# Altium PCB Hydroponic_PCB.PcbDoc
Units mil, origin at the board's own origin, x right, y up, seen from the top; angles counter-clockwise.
Board outline 3600 x 3940 mil, 4 copper layers (SIG 1, GND, SIG 2, PWR), stack 62.508 mil thick; 44 components, 31 nets, 139 pads, 68 vias.
Unrouted connection lines stored in the file: 11.
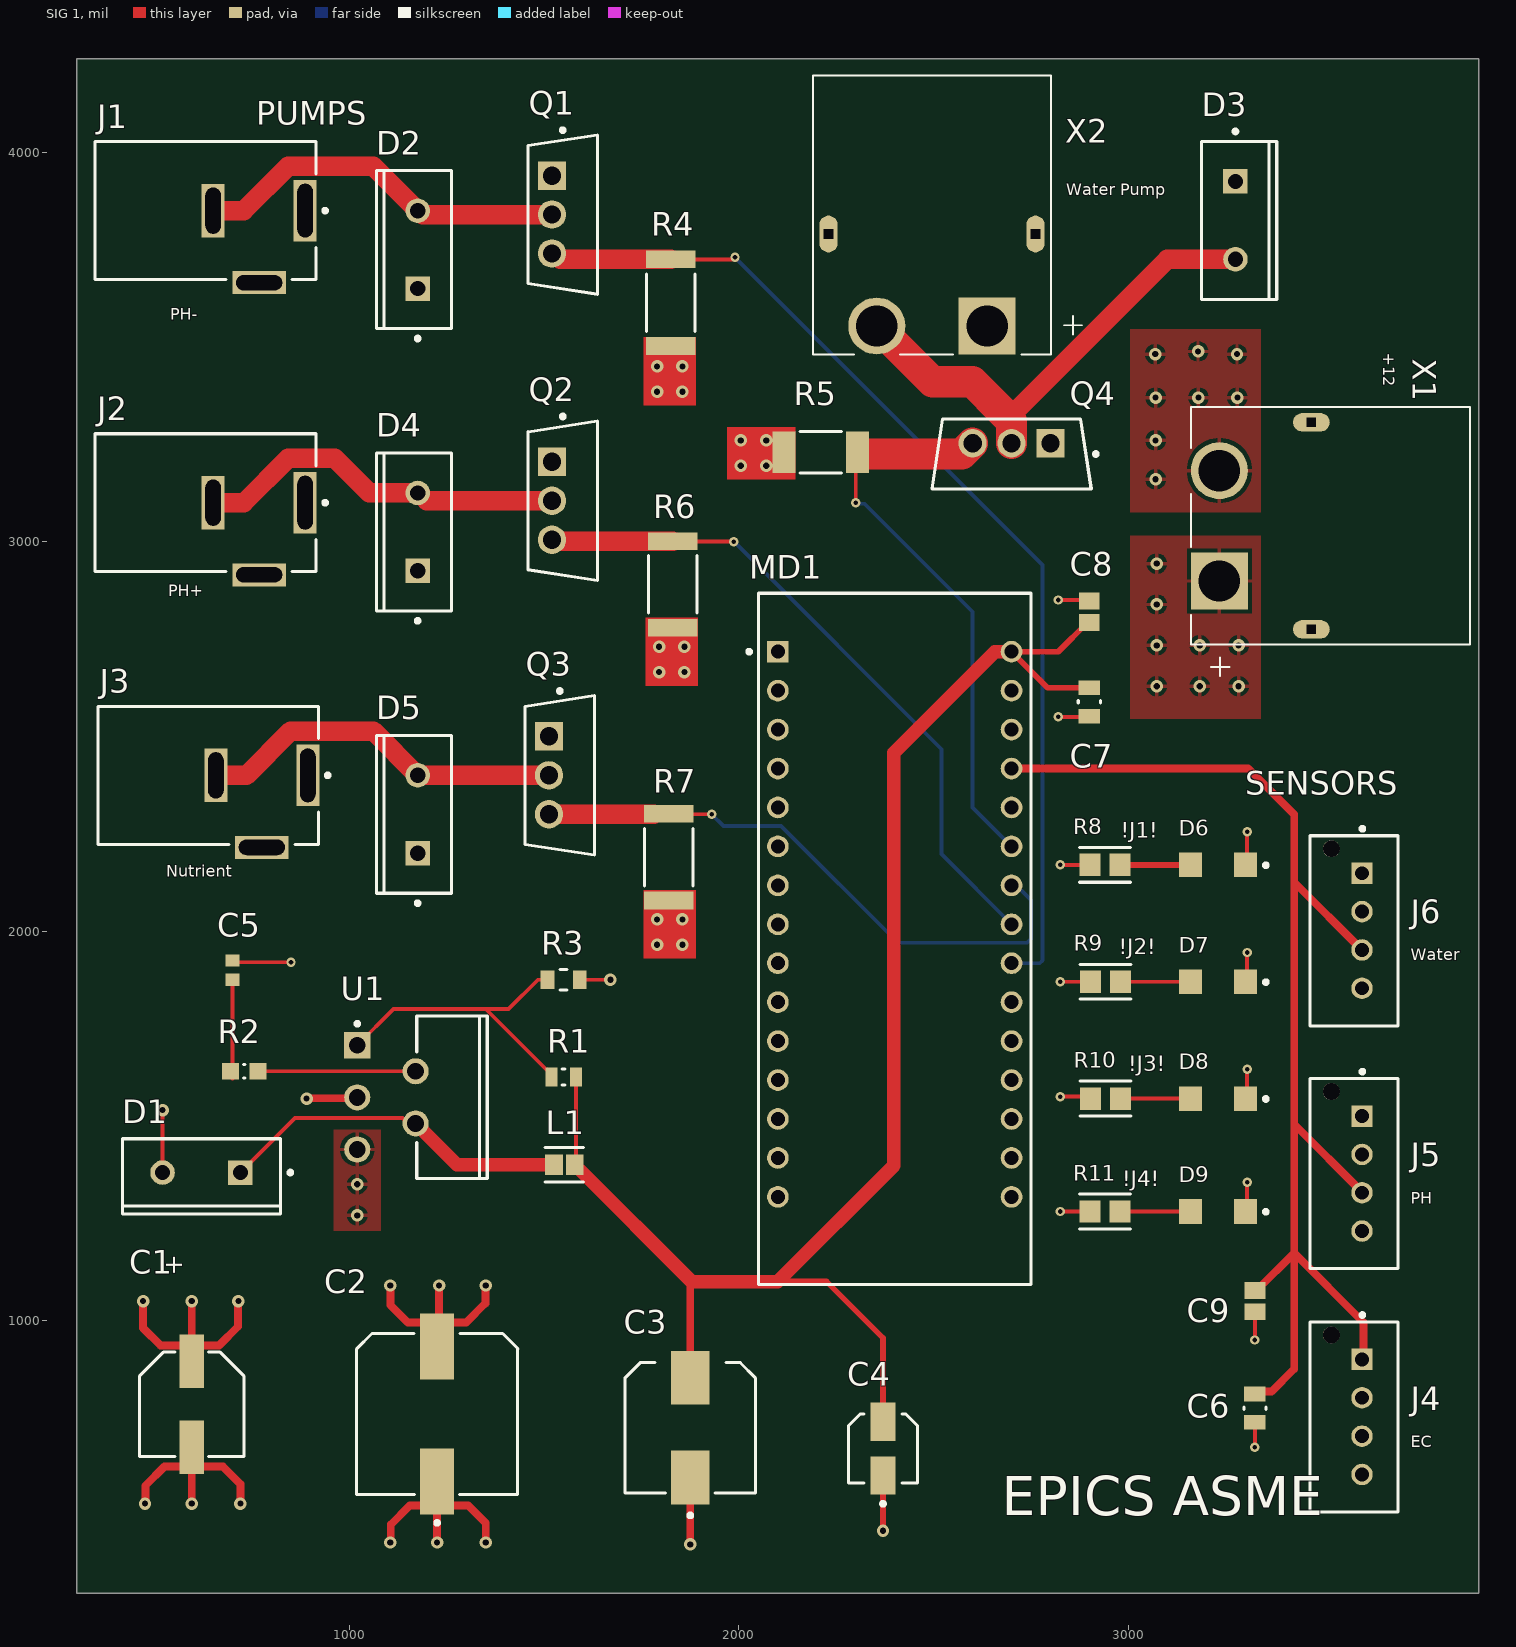
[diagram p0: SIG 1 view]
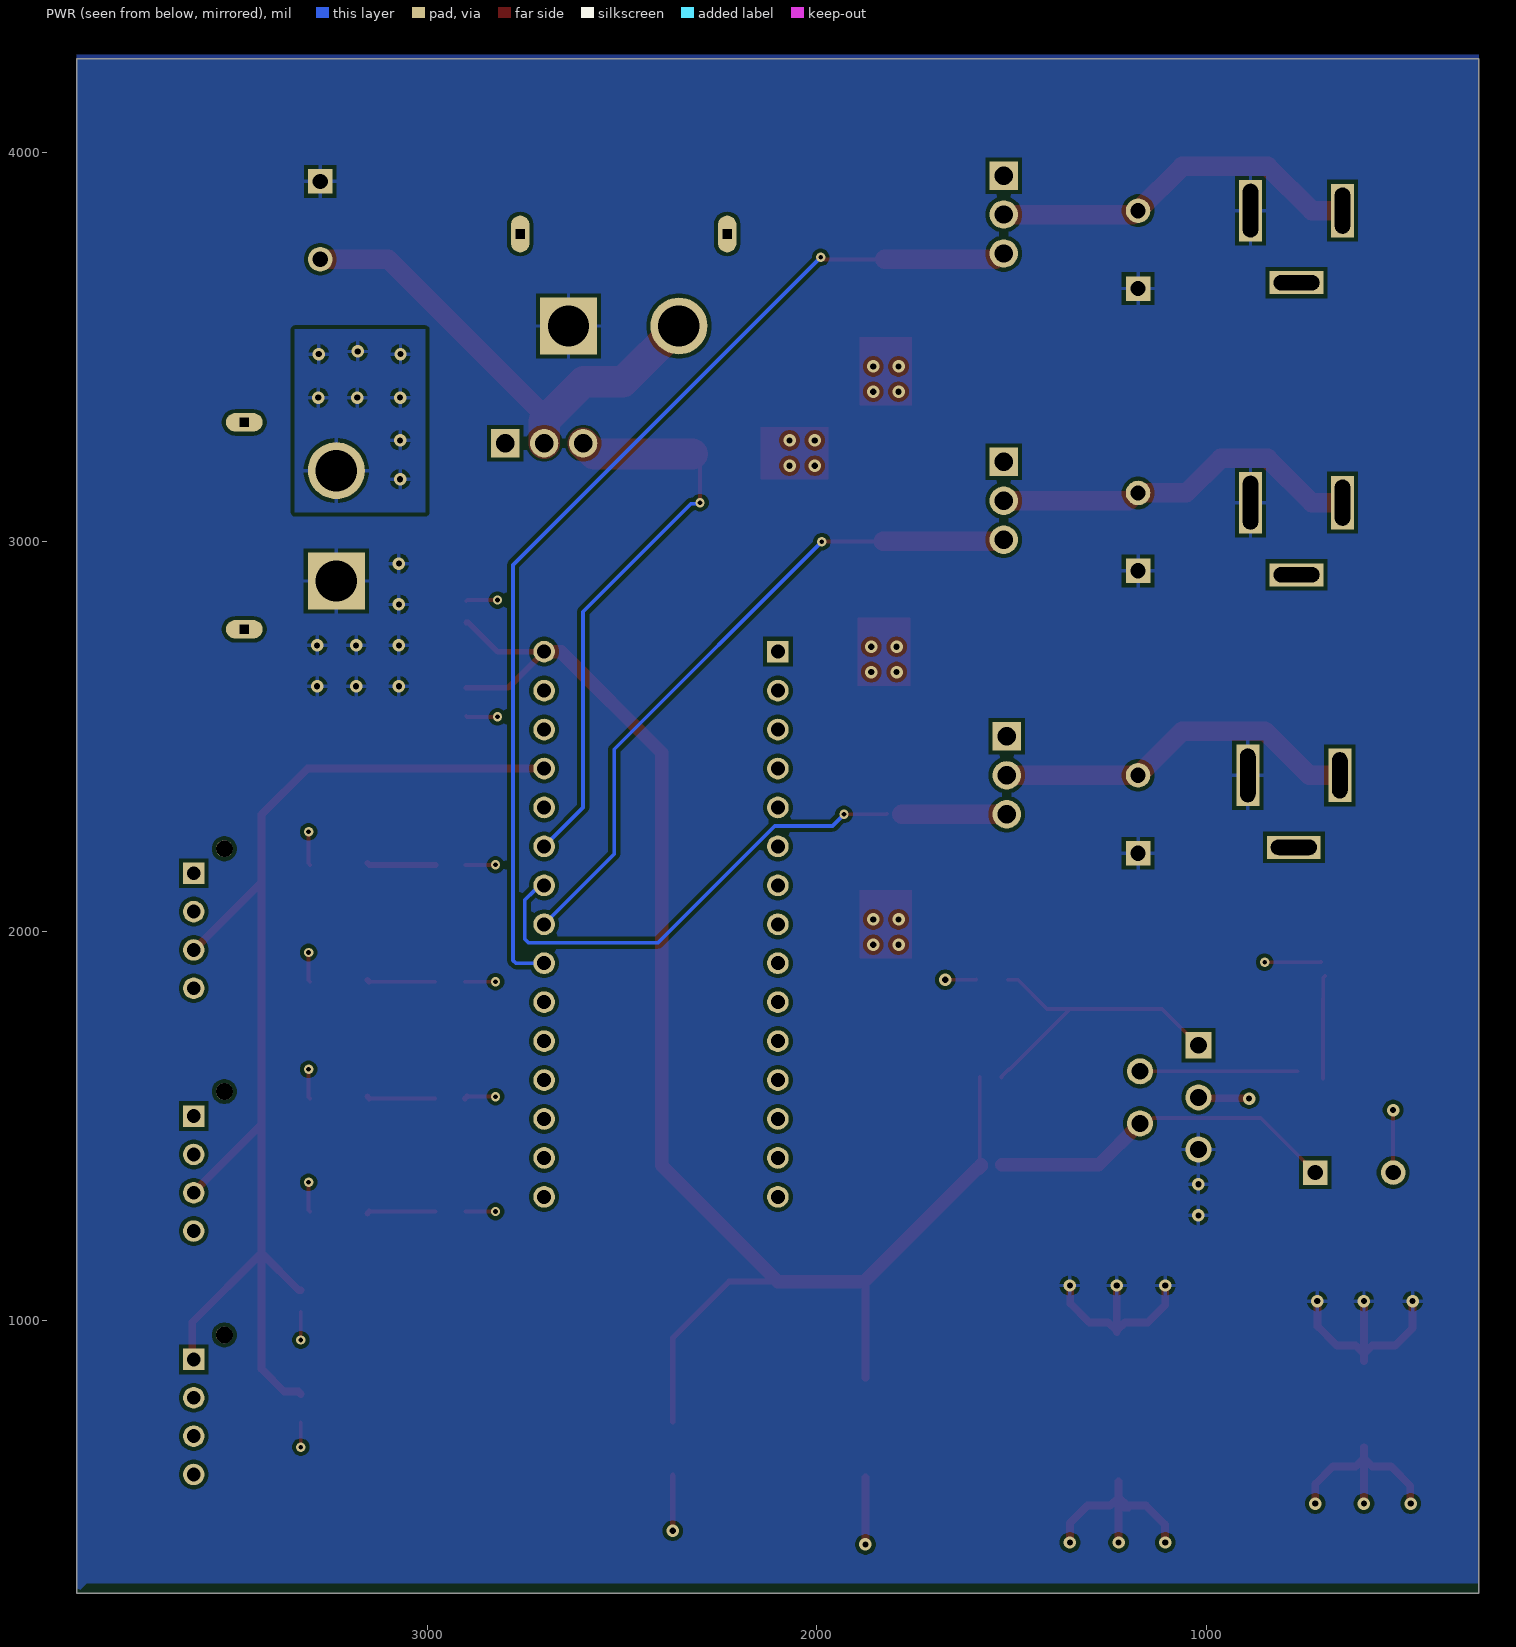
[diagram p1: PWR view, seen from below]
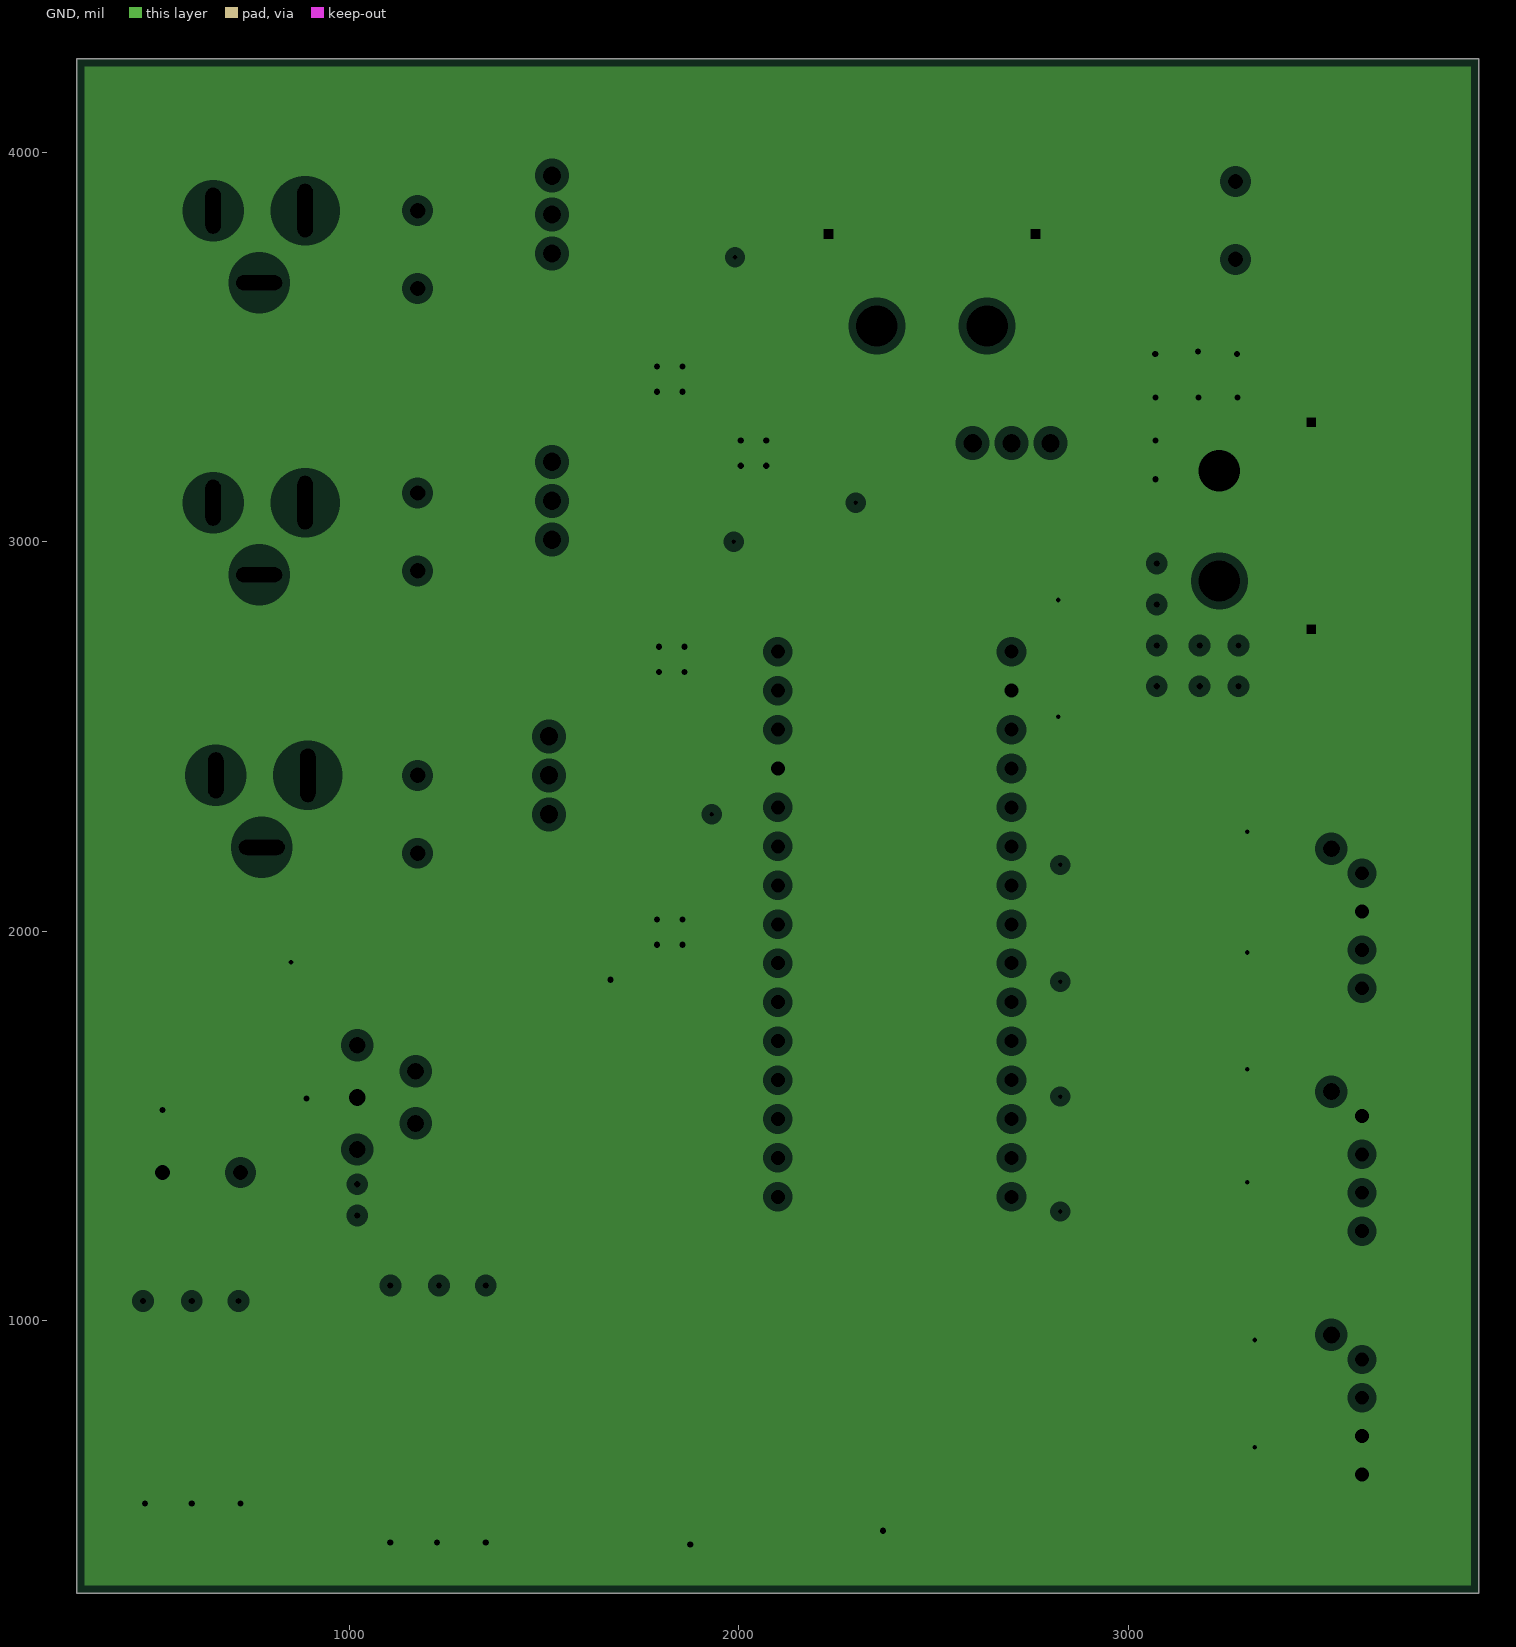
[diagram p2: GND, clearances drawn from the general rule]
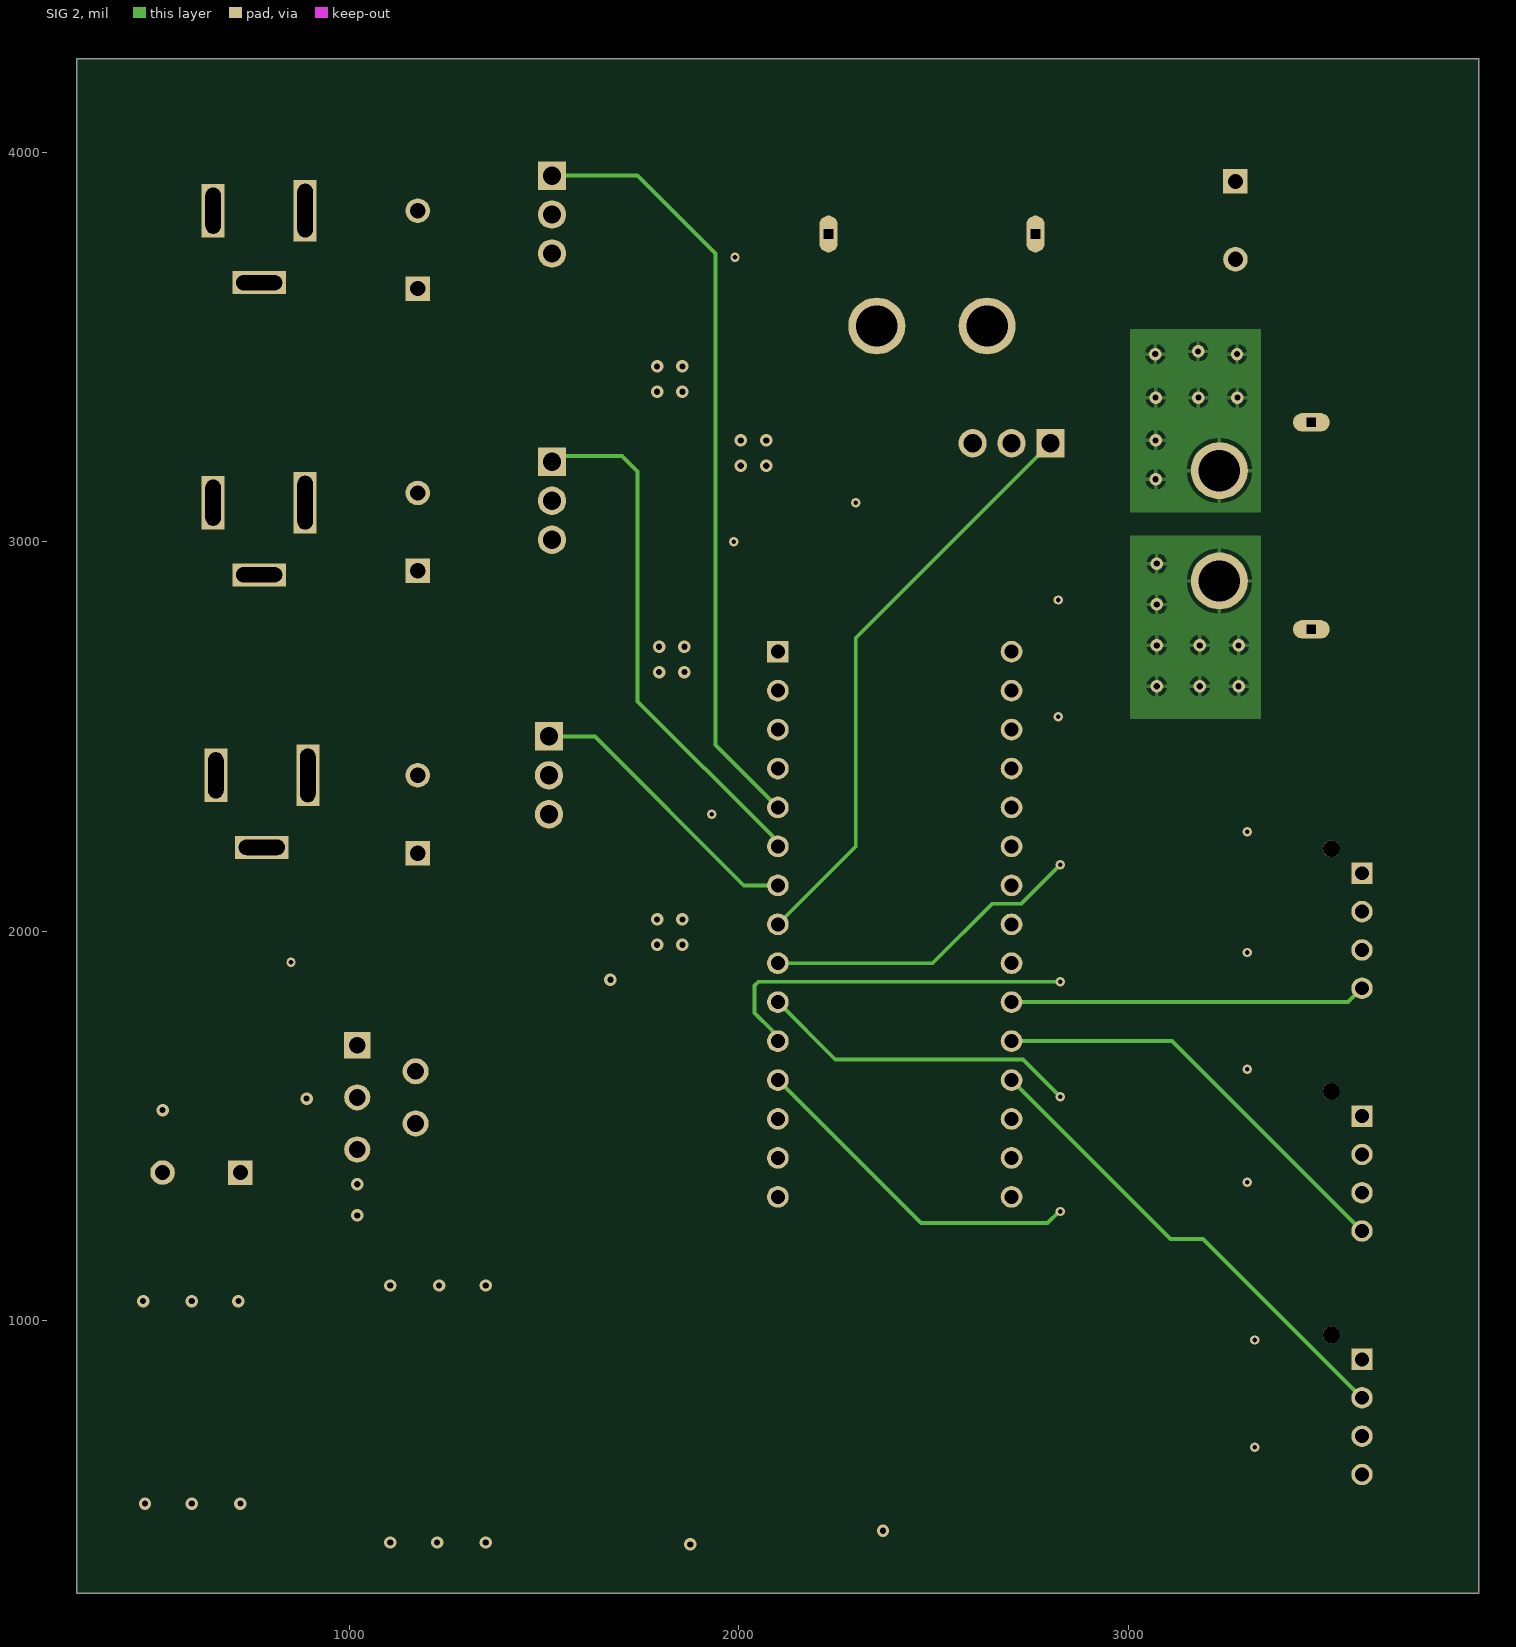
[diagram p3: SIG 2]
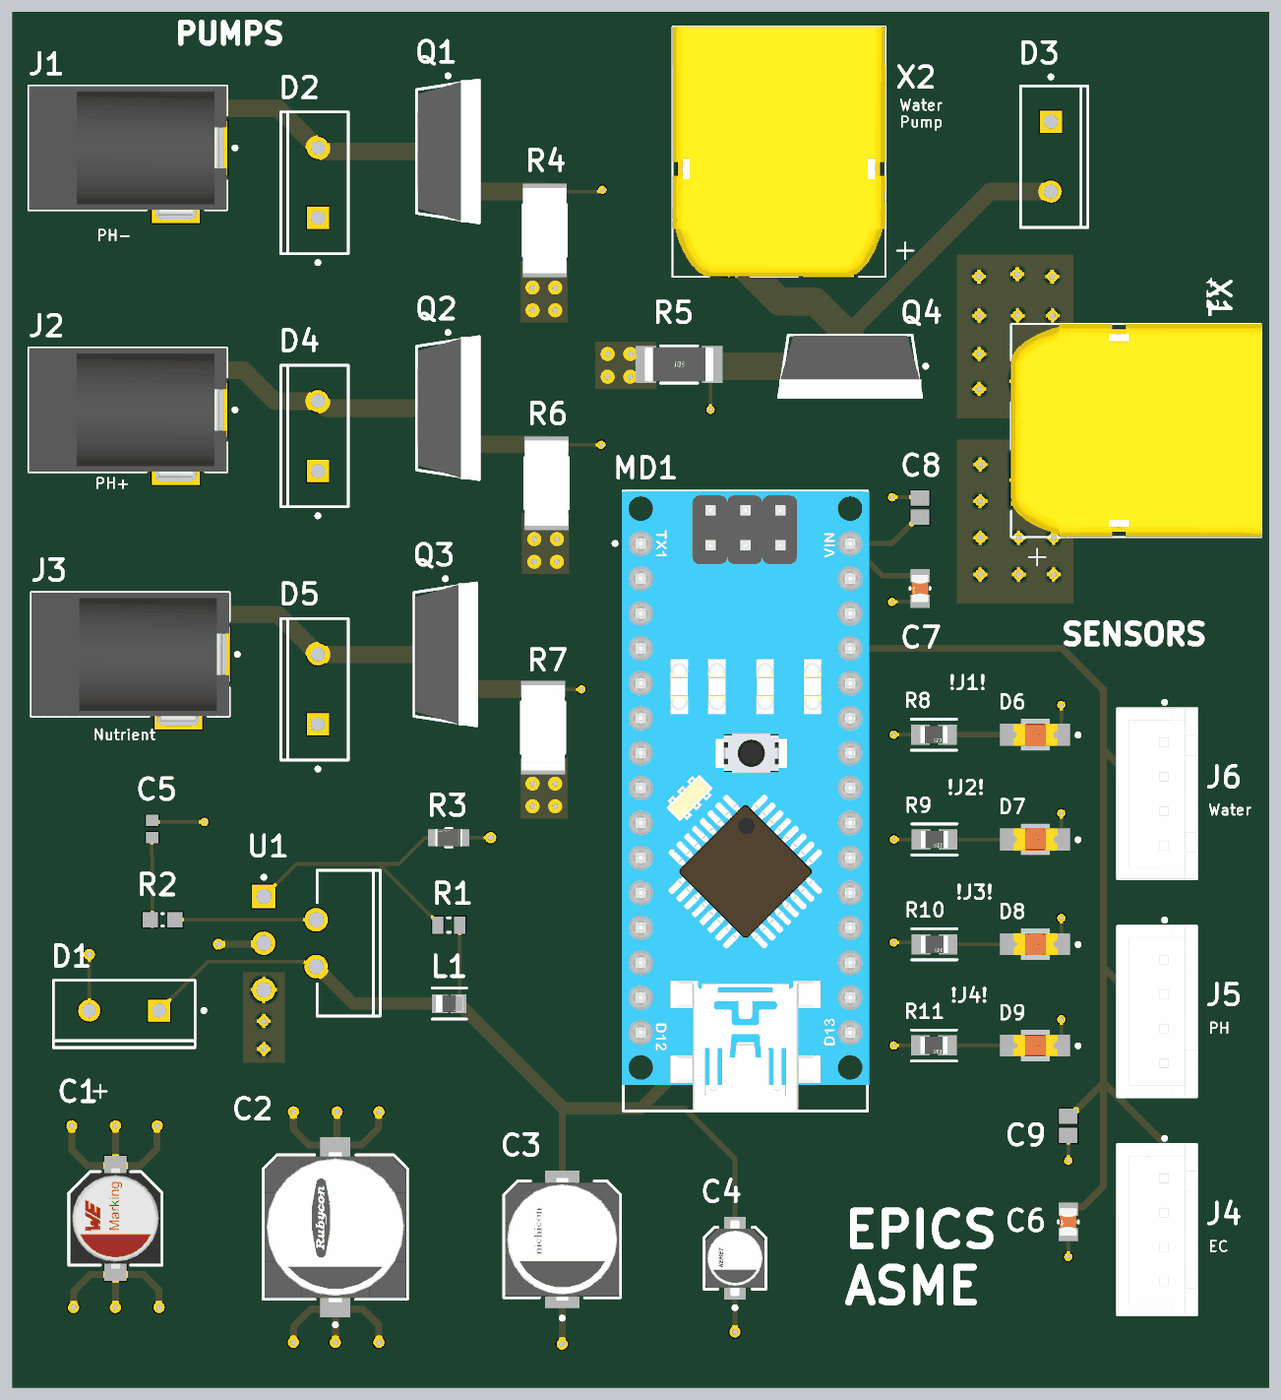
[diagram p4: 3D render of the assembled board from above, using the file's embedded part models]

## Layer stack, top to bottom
Top Solder: solder mask 0.4, Solder Resist, Dk 3.5
SIG 1: signal copper 1.4
Dielectric 1: prepreg 8.2, 7628, Dk 4.5
GND: plane copper 0.689, net GND
Dielectric 2: core 41.93, S1000-2M, Dk 4.3
SIG 2: signal copper 0.689
Dielectric 3: prepreg 8.2, 7628, Dk 4.5
PWR: signal copper 1.4
Bottom Solder: solder mask 0.4, Solder Resist, Dk 3.5

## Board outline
300,300 300,4240 3900,4240 3900,300

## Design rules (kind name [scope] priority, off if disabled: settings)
Clearance Components [InComponent('L1') OR InComponent('C5') OR InComponent('C8') OR InComponent('C9') OR InComponent('R2')] p1: gap=2 ignorepadtopadclearanceinfootprint=FALSE
Clearance GND_clearance [OnLayer('GND')] p2: gap=10 ignorepadtopadclearanceinfootprint=FALSE
Clearance [All] p3: gap=10 ignorepadtopadclearanceinfootprint=FALSE
HoleSize [All] p1: absolutevalues=TRUE maxlimit=150 minlimit=1 maxpercent=80.000 minpercent=20.000
MinimumSolderMaskSliver [All] p1: minsoldermaskwidth=3
PlaneClearance [All] p1: clearance=20
PlaneConnect [All] p1: planeconnectstyle=Relief reliefexpansion=20 reliefentries=4 reliefconductorwidth=10 reliefairgap=10
PolygonConnect [All] p1: connectstyle=Relief reliefconductorwidth=10 reliefentries=4 polygonreliefangle="90 Angle" airgapwidth=10
RoutingVias [All] p1: holewidth=12 width=24 viastyle="Through Hole" minholewidth=10 minwidth=18 maxholewidth=28 maxwidth=50
SilkToSolderMaskClearance [IsPad] p1: minsilkscreentomaskgap=3 clearancetoexposedcopper=TRUE
SolderMaskExpansion [All] p1: expansion=4 istentingtop=FALSE
SupplyNets "Schematic Supply Nets_3" [InNet('+7')] p1: voltage=0.000
SupplyNets "Schematic Supply Nets_2" [InNet('+12')] p2: voltage=0.000
SupplyNets "Schematic Supply Nets_1" [InNet('+5')] p3: voltage=0.000
SupplyNets "Schematic Supply Nets" [InNet('GND')] p4: voltage=0.000
Width [All] p1: maxlimit=100 minlimit=10 preferedwidth=10
25 further rules are at their usual default settings.

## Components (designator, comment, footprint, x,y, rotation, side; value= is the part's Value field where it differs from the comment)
C1 "220 uF" WCAP-ASLL_D6.3H7.7 595,785 r90 top
C2 "100 uF" FP-TGV10X10_5-MFG 1225,760 r90 top
C3 "47 uF" FP-UUX1H470MNL6GS-MFG 1875,725 r90 top
C4 "10 uF" FP-EDK9B-MFG 2370,671.1 r90 top value=10uF
C5 "10 nF" CAPC1608X87X35LL15T15 700,1900 r90 top
C6 "1 uF" FP-CC0805-0_85-MFG 3325,775 r270 top
C7 "1 uF" FP-CC0805-0_85-MFG 2900,2588.58 r270 top
C8 "100 nF" CAPC2013X140X50LL20T25 2900,2820 r270 top
C9 "100 nF" CAPC2013X140X50LL20T25 3325,1050 r90 top
D1 "MBR1060G" ONSC-TO-220-2-221B-04_E 620,1380 r270 top
D2 "MBR1060G" ONSC-TO-220-2-221B-04_E 1175,3750 r180 top
D3 "MBR1060G" ONSC-TO-220-2-221B-04_E 3275,3825 r0 top
D4 "MBR1060G" ONSC-TO-220-2-221B-04_E 1175,3025 r180 top
D5 "MBR1060G" ONSC-TO-220-2-221B-04_E 1175,2300 r180 top
D6 "LTST-C230EKT" FP-LTST-C230EKT-MFG 3230,2170 r180 top
D7 "LTST-C230EKT" FP-LTST-C230EKT-MFG 3230,1870 r180 top
D8 "LTST-C230EKT" FP-LTST-C230EKT-MFG 3230,1570 r180 top
D9 "LTST-C230EKT" FP-LTST-C230EKT-MFG 3230,1280 r180 top
J1 "PJ-002A" CUI-PJ-002A_V 768.11,3850 r180 top
J2 "PJ-002A" CUI-PJ-002A_V 768.11,3100 r180 top
J3 "PJ-002A" CUI-PJ-002A_V 775,2400 r180 top
J4 "PH Sensor Connector" FP-B4B-XH-AM_LF_SN-MFG 3579.33,752.36 r90 top
J5 "EC Sensor Connector" FP-B4B-XH-AM_LF_SN-MFG 3579.33,1377.36 r90 top
J6 "Water sensor 1" FP-B4B-XH-AM_LF_SN-MFG 3579.33,2000.79 r90 top
L1 "100 uH" FP-LQM21DH_70-IPC_C 1551.61,1400 r0 top
MD1 "A000005" FP-A000005-MFG 2400,1980 r0 top
Q1 "IRLZ44NPbF" FP-PG-TO220-3-MFG 1547.76,3840 r0 top
Q2 "IRLZ44NPbF" FP-PG-TO220-3-MFG 1547.76,3105 r0 top
Q3 "IRLZ44NPbF" FP-PG-TO220-3-MFG 1540,2400 r0 top
Q4 "IRLZ44NPbF" FP-PG-TO220-3-MFG 2700,3225 r270 top
R1 "1k" RESC2013X60X35LL10T20 1550,1625 r0 top
R2 "2.7k" RESC0603(1608)_M 730,1640 r0 top value="2700.00 Ohm"
R3 "2.2k" FP-AC0805-MFG 1550,1875 r180 top value=2.2KΩ
R4 "1" FP-CRCW2512-e3-IPC_C 1825,3613.75 r270 top
R5 "0.1" FP-CSRN2010-IPC_A 2210,3230 r180 top
R6 "1" FP-CRCW2512-e3-IPC_C 1830,2890 r270 top
R7 "1" FP-CRCW2512-e3-IPC_C 1820,2190 r270 top
R8 "220" FP-RMCF0805-IPC_A 2940,2170 r0 top
R9 "220" FP-RMCF0805-IPC_A 2941.58,1870 r0 top
R10 "220" FP-RMCF0805-IPC_A 2941.58,1570 r0 top
R11 "220" FP-RMCF0805-IPC_A 2940,1280 r0 top
U1 "LT1076IT" LT-T-5-S 1095,1573.07 r0 top
X1 "X1" PCBComponent_1 1631.26,1524.84 r90 top
X2 "X2" PCBComponent_1 4011.65,1951.26 r180 top

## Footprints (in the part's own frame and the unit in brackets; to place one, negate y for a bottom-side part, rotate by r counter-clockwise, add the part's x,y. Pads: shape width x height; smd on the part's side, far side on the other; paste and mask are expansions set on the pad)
CAPC1608X87X35LL15T15 [mm] "Chip Capacitor, 2-Leads, Body 1.60x0.80mm, IPC High Density"
  rect 0.8x0.9 smd: 1(-0.625,0) 2(0.625,0)
  body extent -0.87,-0.48 0.87,0.48, height 0.87
CAPC2013X140X50LL20T25 [mm] "Chip Capacitor, 2-Leads, Body 2.00x1.25mm, IPC High Density"
  rect 1.1x1.35 smd: 1(-0.7,0) 2(0.7,0)
  body extent -1.1,-0.72 1.1,0.72, height 1.4
CUI-PJ-002A_V [mm] "THD, 3-Leads, Body 14.4x9mm, Height 11mm"
  rect 1.5x4 hole 1 slot 3.5 at 90 deg: 1(-3,0)
  rect 1.5x3.5 hole 1 slot 3 at 90 deg: 2(3,0)
  rect 3.5x1.5 hole 1 slot 3 at 0 deg: 3(0,4.7)
  silkscreen extent -4.43,-4.5 10.7,4.5, body extent -3.7,-4.5 10.7,4.9, height 11
FP-A000005-MFG [mil]
  rect 55.67x55.67 hole 35.98 paste-99999 mask+0: 1(-300,737.5)
  round 55.67 hole 35.98 paste-99999 mask+0: 2(-300,637.5) 3(-300,537.5) 4(-300,437.5) 5(-300,337.5) 6(-300,237.5) 7(-300,137.5) 8(-300,37.5) 9(-300,-62.5) 10(-300,-162.5) 11(-300,-262.5) 12(-300,-362.5) 13(-300,-462.5) 14(-300,-562.5) 15(-300,-662.5) 16(300,-662.5) 17(300,-562.5) 18(300,-462.5) 19(300,-362.5) 20(300,-262.5) 21(300,-162.5) 22(300,-62.5) 23(300,37.5) 24(300,137.5) 25(300,237.5) 26(300,337.5) 27(300,437.5) 28(300,537.5) 29(300,637.5) 30(300,737.5)
  silkscreen extent -379,-888 350,888, body extent -354,-891 354,891, height 10
FP-AC0805-MFG [mm]
  rect 0.9x1.2 smd paste+0 mask+0: 1(-1.05,0) 2(1.05,0)
  silkscreen extent -0.23,-0.67 0.23,0.67, body extent -1.6,-0.77 1.6,0.77, height 0.25
FP-B4B-XH-AM_LF_SN-MFG [mm]
  rect 1.4x1.4 hole 0.9 paste-2539.97 mask+0: 1(3.75,-0.525)
  round 1.4 hole 0.9 paste-2539.97 mask+0: 2(1.25,-0.525) 3(-1.25,-0.525) 4(-3.75,-0.525)
  round 1.1 hole 1.1 unplated paste-2539.97 mask+0: ""(5.35,1.475)
  silkscreen extent -6.2,-2.88 6.77,2.88, body extent -6.3,-2.98 6.3,2.98, height 0.25
FP-CC0805-0_85-MFG [mm]
  rect 0.95x1.4 smd paste+0 mask+0: 1(-0.925,0) 2(0.925,0)
  silkscreen extent -0.08,-0.72 0.08,0.72, body extent -1.6,-1.05 1.6,1.05, height 0.25
FP-CRCW2512-e3-IPC_C [mil]
  rect 45.47x126.31 smd paste+0 mask+0: 1(-111.25,0) 2(111.25,0)
  silkscreen extent -74,-62 74,62, body extent -138,-69 138,69, height 10
FP-CSRN2010-IPC_A [mil]
  rect 59.24x106.62 smd paste+0 mask+0: 1(-94.52,0) 2(94.52,0)
  silkscreen extent -53,-53 53,53, body extent -144,-73 144,73, height 10
FP-EDK9B-MFG [mm]
  rect 2.5x1.6 smd paste+0 mask+0: 1(-1.75,0) 2(1.75,0)
  silkscreen extent -3.72,-2.25 2.25,2.25, body extent -3.25,-2.5 3.25,2.5, height 0.25
FP-LQM21DH_70-IPC_C [mil]
  rect 45.45x53.39 smd paste+0 mask+0: 1(-26.61,0) 2(26.61,0)
  silkscreen extent -49,-44 49,44, body extent -53,-32 53,32, height 10
FP-LTST-C230EKT-MFG [mm]
  rect 1.5x1.6 smd paste+0 mask+0: 1(-1.8,0) 2(1.8,0)
  silkscreen extent -3.25,-0.1 -3,0.15, body extent -2.65,-0.95 2.65,0.95, height 0.25
FP-PG-TO220-3-MFG [mm]
  rect 1.85x1.85 hole 1.2 paste-2539.97 mask+0: 1(-0.705,2.54)
  round 1.85 hole 1.2 paste-2539.97 mask+0: 2(-0.705,0) 3(-0.705,-2.54)
  silkscreen extent -2.27,-5.2 2.27,5.62, body extent -2.37,-5.55 2.37,5.55, height 0.25
FP-RMCF0805-IPC_A [mil]
  rect 53.33x57.56 smd paste+0 mask+0: 1(-38.42,0) 2(38.42,0)
  silkscreen extent -65,-45 65,45, body extent -85,-48 85,48, height 10
FP-TGV10X10_5-MFG [mm]
  rect 4.3x2.2 smd paste+0 mask+0: 1(-4.4,0) 2(4.4,0)
  silkscreen extent -7.22,-5.28 5.25,5.25, body extent -6.8,-5.5 6.8,5.5, height 0.25
FP-UUX1H470MNL6GS-MFG [mm]
  rect 3.5x2.5 smd paste+0 mask+0: 1(-3.25,0) 2(3.25,0)
  silkscreen extent -5.85,-4.25 4.26,4.25, body extent -5.25,-4.5 5.25,4.5, height 0.25
LT-T-5-S [mm] "FM, 5-Leads, Body 10.55x4.6mm, Pitch 1.7mm"
  rect 1.7x1.7 hole 1.1: 1(-1.905,3.4)
  round 1.7 hole 1.1: 2(1.905,1.7) 3(-1.905,0) 4(1.905,-1.7) 5(-1.905,-3.4)
  silkscreen extent -2.03,-5.3 6.58,5.3, body extent -2.13,-5.27 6.58,5.28, height 22.23
ONSC-TO-220-2-221B-04_E [mm] "FM, 2-Leads, Body 10.3x4.85mm, Pitch 5.08mm"
  rect 1.6x1.6 hole 1: 1(0,2.54)
  round 1.6 hole 1: 3(0,-2.54)
  silkscreen extent -2.2,-5.15 2.7,5.93, body extent -2.18,-5.15 2.67,5.15, height 19.05
PCBComponent_1 [mm]
  rect 3.716x3.716 / inner round 3.716 / far side rect 3.716x3.716 hole 2.7 mask+0.102: 1(34.904,-40.704)
  round 3.716 hole 2.7 mask+0.102: 2(42.104,-40.704)
  oval 1.2x2.4 hole 0.6 square mask+0.102: SH1(31.754,-46.704) SH2(45.254,-46.704)
  silkscreen extent 28.7,-57.05 46.25,-38.85, body extent 30.75,-57.05 46.25,-38.85, height 8.4
RESC0603(1608)_M [mm] "Chip Resistor, Body 1.6x0.8mm, IPC Low Density"
  rect 1.1x1.1 smd: 1(-0.9,0) 2(0.9,0)
  silkscreen extent -0.05,-0.45 0.05,0.45, body extent -0.85,-0.47 0.85,0.47, height 0.6
RESC2013X60X35LL10T20 [mm] "Chip Resistor, 2-Leads, Body 2.00x1.25mm, IPC High Density"
  rect 0.8x1.25 smd: 1(-0.8,0) 2(0.8,0)
  silkscreen extent -0.1,-0.53 0.1,0.53, body extent -1.05,-0.67 1.05,0.67, height 0.6
WCAP-ASLL_D6.3H7.7 [mm] "Aluminium Electrolytic V-Chip SMT Capacitors, 6.3x7.7mm"
  rect 3.5x1.6 smd: 1(2.8,0) 2(-2.8,0)
  silkscreen extent -3.4,-3.4 3.4,3.4, body extent -3.65,-3.3 3.65,3.3, height 7.7

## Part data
C1: library part CMP-03913-53914500-3, Capacitance=220µF, Case/Package=Radial, ESR (Equivalent Series Resistance)=246.927mΩ, Insulation Resistance=454.545kΩ, Leakage Current=13.86µA, Max Operating Temperature=105°C, Min Operating Temperature=-55°C, Ripple Current=280mA, Tolerance=20%, Voltage Rating=6.3V
C2: library part CMP-35376-000017-1, "CAP ALUM 100UF 20% 35V SMD"
C3: library part CMP-12462-000056-1, "CAP ALUM 47UF 20% 50V SMD", Capacitance=47uF, Case/Package=Radial, Leakage Current=70.5uA, Max Operating Temperature=105°C, Min Operating Temperature=-55°C, Package Quantity=1, Ripple Current=167mA, Tolerance=20%, Voltage=50V
C4: library part CMP-03015-000003-1, "CAP ALUM 10UF 20% 35V SMD", Capacitance=10uF, Leakage Current=3.5uA, Manufacturer=Kemet, Manufacturer Part Number=EDK106M035A9BAA, Package=EDK9B, Ripple Current=24mA, Temperature="-40°C to +85°C", Temperature Range High=+85°C, Temperature Range Low=-40°C, Tolerance=20%, Voltage Rating=35V
C5: library part CMP-2006-03842-1, Manufacturer=Kemet, Part Number=C0603S103K4RACTU
C6 C7: library part CMP-03422-000746-1, "CAP CER 1UF 10V X5R 0805", Manufacturer=Yageo, Manufacturer Part Number=CC0805KKX5R6BB105, Package=CC0805-0.85, Temperature="-30°C to +85°C", Temperature Characteristic=X5R, Temperature Range High=+85°C, Temperature Range Low=-30°C, Tolerance=0.1, Voltage Rating="10 V"
C8 C9: library part CMP-2007-04740-1, Manufacturer="AVX Interconnect / Elco", Part Number=08051C104M4Z2A
D1 D2 D3 D4 D5: library part CMP-1055-00607-1, "SWITCHMODE(TM) Power Rectifier, 2-Pin TO-220, Pb-Free, Tube", Manufacturer="On Semiconductor"
D6 D7 D8 D9: library part CMP-22017-000030-1, "LED RED CLEAR CHIP SMD", Case Code (Imperial)=1206, Case Code (Metric)=3216, Color=Red, Forward Current=30mA, Forward Voltage=2V, Lens Color=Colorless, Max Operating Temperature=85°C, Min Operating Temperature=-55°C, Package Quantity=1, Power Dissipation=100mW, Reverse Voltage=5V, Test Current=10mA
J1 J2 J3: library part CMP-2000-06895-2, "Through Hole Right Angle DC Power Jack, 2.5 A, 2 mm Center Pin, 3 Position, -25 to 85 degC, RoHS, Bulk", Current Rating=2.5A, Flammability Rating=UL94V-0, Insulation Resistance=50MOhms, Manufacturer=CUIInc., Operating Temperature Range=-25Cto+85C, Package Description="3-Pin Through Hole Device, Body 14.4 x 9 mm, Height 11 mm", Voltage Rating=24V
J4 J5 J6: library part CMP-17439-000117-1, "CONN HEADER VERT 4POS 2.5MM", Color=Green, Contact Resistance=20mR, Flammability Rating="UL94 V-0", Housing Color=White, Insulation Color=Natural, Max Current Rating=3A, Max Operating Temperature=85°C, Max Voltage Rating (AC)=250V, Min Operating Temperature=-25°C
L1: library part CMP-06042-017057-1, "Multilayer type Inductor for Power Lines for Automotive 100uH ±20% @1MHz, 160mA, Max DCR 4.095Ω, SRF 8MHz"
MD1: library part CMP-189986-000002-1, "ARDUINO NANO ATMEGA328 EVAL BRD", Operating Supply Voltage=12V, Package Quantity=50
Q1 Q2 Q3 Q4: library part CMP-32901-000488-1, "MOSFET N-CH 55V 47A TO220AB", Case/Package=TO-220, Continuous Drain Current (ID)=47A, Drain to Source Breakdown Voltage=55V, Drain to Source Resistance=35mR, Gate to Source Voltage (Vgs)=16V, Input Capacitance=1.7nF, Max Operating Temperature=175°C, Max Power Dissipation=110W, Min Operating Temperature=-55°C, Threshold Voltage=2V
R1: library part CMP-2001-01418-1, Manufacturer=Yageo, Part Number=RC0805JR-131KL
R2: library part CMP-1012-00084-1, "2K7 0.1W 5% 0603 (1608 Metric)  SMD", Case-EIA=0603, Case-Metric=1608, Power="0.1 W", Tolerance="5 %"
R3: library part CMP-03412-037614-1, "RES SMD 2.2K OHM 5% 1/8W 0805", Manufacturer=Yageo, Manufacturer Part Number=AC0805JR-072K2L, Package=AC0805, Power Rating=1/8W, Resistance=2.2KΩ, Temperature="-55°C to +155°C", Temperature Range High=+155°C, Temperature Range Low=-55°C, Tolerance=0.05, Voltage Rating=150V
R4 R6 R7: library part CMP-02407-008720-1, "RES Thick Film, 1Ω, 1%, 1W, 100ppm/°C, 2512", Case/Package=2512, Max Operating Temperature=155°C, Max Power Dissipation=1W, Min Operating Temperature=-55°C, Resistance=1R, Temperature Coefficient=100ppm/°C, Tolerance=1%
R5: library part CMP-26527-001368-1, "Res Thick Film 2010 0.1Ω 1% 1W ±250ppm/°C Molded SMD Plastic T/R", Case/Package=2010, Max Operating Temperature=155°C, Max Power Dissipation=1W, Min Operating Temperature=-55°C, Package Quantity=4000, Resistance=100mR, Resistor Type="Thick Film", Temperature Coefficient=250ppm/°C, Tolerance=1%
R8 R9 R10 R11: library part CMP-26527-006932-1, "220Ω ±5% 0.125W 0805 Thick Film Chip Resistor AEC-Q200 compliant", Case Code (Imperial)=0805, Case Code (Metric)=2012, Max Operating Temperature=155°C, Max Power Dissipation=125mW, Min Operating Temperature=-55°C, Resistance=220R, Resistor Type="Thick Film", Temperature Coefficient=200ppm/°C, Tolerance=5%
U1: library part CMP-0491-02059-1, "Step-Down Switching Regulator, 5-pin FM (T-5), -40 to 85 degC", Manufacturer="Linear Technology"
X1 X2: library part xt60

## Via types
v1: diameter 32, hole 16, SIG 1 to PWR, 51 vias
v2: diameter 24, hole 12, SIG 1 to PWR, 17 vias

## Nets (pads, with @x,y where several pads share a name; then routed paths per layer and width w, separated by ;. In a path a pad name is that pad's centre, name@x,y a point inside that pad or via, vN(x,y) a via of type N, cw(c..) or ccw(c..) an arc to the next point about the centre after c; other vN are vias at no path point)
+5: C6.1 C9.2 J4.1 J5.3 J6.3 MD1.27 | length 3311.1
  SIG 1 w20: MD1.27 3307.5,2417.5 3425.79,2299.21 3425.79,2125.79 ; C6.1 3331.13,817.55 3367.55,817.55 3425.79,875.79 3425.79,1074.21 3425.79,1115.8 3425.79,1173.43 ; C9.2 3329.92,1077.56 3425.79,1173.43 ; J5.3@3600,1330 3425.79,1504.21 ; J6.3 3425.79,2125.79 ; J4.1@3603.54,894.88 3603.54,995.67 3425.79,1173.43 ; 3425.79,1173.43 3425.79,1175 3425.79,1504.21 ; 3425.79,1504.21 3425.79,2125.79
+7: C3.2 C4.2 C7.1 C8.2 L1.2 MD1.30 R1.2 | length 4028.5
  SIG 1 w10: L1.2 1581.5,1403.28 R1.2
  SIG 1 w15: 1875,1096.78 1878.22,1100 ; 2100,1100 2225,1100 2370,955 C4.2 ; C7.1 2792.5,2625 MD1.30 2820.14,2717.5 2895.08,2792.44 C8.2
  SIG 1 w20: C3.2 1875,1096.78
  SIG 1 w35: L1.2 1578.22,1396.03 1583.44,1390.8 1587.42,1390.8 1878.22,1100 2100,1100 2398.02,1398.02 2398.02,2458.02 2656.94,2716.94 2699.44,2716.94 MD1.30
+12: C1.1 C2.2 D2.1 D3.1 D4.1 D5.1 J1.1 J2.1 J3.1 U1.5 X1.1 X2.1 | length 1107.3
  SIG 1 w20: v1(470,1050) 470,980.88 515,935.88 573.5,935.88 C1.1@595,914.38 ; C1.1 C1.1@595,914.38 ; v1(595,1050) C1.1@595,914.38 ; v1(715,1050) 714,1049 714,984.88 665,935.88 616.5,935.88 C1.1@595,914.38 ; v1(1105,1090) 1105,1040 1150,995 1208.5,995 1230,973.5 1251.5,995 1300,995 1349,1044 1349,1089 v1(1350,1090) ; C2.2@1230,970 v1(1230,1090)
  other v1: 1020,1270 1020,1350 3073.08,2628.69 3183.08,2628.69 3283.08,2628.69 3073.08,2733.69 3183.08,2733.69 3283.08,2733.69 3073.08,2838.69 3073.08,2943.69
A_EC: J5.4 MD1.20 | length 1102
  SIG 2 w10: MD1.20 3112.22,1717.5 J5.4
GND: C1.2 C2.1 C3.1 C4.1 C5.2 C6.2 C7.2 C8.1 C9.1 D1.3 D6.1 D7.1 D8.1 D9.1 J4.3 J4.4 J5.1 J6.2 MD1.4 MD1.29 R3.1 R4.2 R5.2 R6.2 R7.2 U1.3 X1.2 X1.SH1 X1.SH2 X2.SH1 X2.SH2 | length 2566.1
  SIG 1 w10: D1.3 v1@520,1540 ; C5.2@705.21,1920.29 705.51,1920 v2(850,1920) ; R3.1@1590.67,1875.67 R3.1 v1(1670,1875) ; v2(2820,2550) 2897.83,2550 C7.2 ; v2(2820,2850) 2897.56,2850 C8.1 ; D9.1 3305,1284.13 v2(3305,1355) ; D8.1 3305,1574.13 v2(3305,1645) ; D7.1 3305,1874.13 v2(3305,1945) ; D6.1 3305,2174.13 v2(3305,2255) ; v2(3325,675) C6.2 ; v2(3325,950) C9.1
  SIG 1 w15: v1(2370,460) C4.1
  SIG 1 w20: v1(475,530) 476,531 476,576 525,625 573.5,625 595,646.5 616.5,625 675,625 720,580 v1(720,530) ; v1(595,530) C1.2 ; v1(890,1570) 890.77,1570.77 1017.69,1570.77 U1.3 ; v1(1105,430) 1106,431 1106,476 1155,525 1203.5,525 1225,546.5 1246.5,525 1305,525 1350,480 v1(1350,430) ; C2.1@1199.57,520 C2.1@1225,520 ; v1(1225,430) C2.1 ; v1(1875,425) C3.1
  other v1: 520.09,1540.5 1790,1965 1855,1965 1790,2030 1855,2030 1795,2665 1860,2665 1795,2730 1860,2730 3070,3160 2005,3195 2070,3195 2005,3260 2070,3260 3070,3260 3070,3370 3180,3370 3280,3370 1790,3385 1855,3385 1790,3450 1855,3450 3069,3481.58 3279,3481.58 3179,3488.42
NetC5_1: C5.1 R2.1 | length 267.2
  SIG 1 w10: C5.1@695,1885 699.57,1880.43 699.57,1824.96 700,1825.39 R2.1@700,1620.78
NetD1_1: D1.1 L1.1 U1.4 | length 912.7
  SIG 1 w10: D1.1 860,1520 1135.68,1520 1138.64,1517.03 1159.11,1517.03 U1.4
  SIG 1 w35: U1.4 1276.14,1400 L1.1
NetD2_3: D2.3 J1.2 Q1.2 | length 968.4
  SIG 1 w50: J1.2 728.46,3850 842.2,3963.74 1061.26,3963.74 D2.3 1178.52,3850 1188.52,3840 Q1.2
NetD3_3: D3.3 Q4.2 X2.2 | length 1258.1
  SIG 1 w50: 2704.37,3310 2704.37,3329.37 3100,3725 D3.3
  SIG 1 w80: X2.2 2497.23,3410.56 2599.44,3410.56 2677.5,3332.5 2700,3310 Q4.2
NetD4_3: D4.3 J2.2 Q2.2 | length 962.2
  SIG 1 w50: J2.2 728.46,3100 842.2,3213.74 962.47,3213.74 1051.21,3125 D4.3 1178.52,3125 1198.52,3105 Q2.2
NetD5_3: D5.3 J3.2 Q3.2 | length 949.6
  SIG 1 w50: J3.2 735.35,2400 849.09,2513.74 1061.26,2513.74 D5.3 Q3.2
NetD6_2: D6.2 R8.2 | length 177.8
  SIG 1 w15: R8.2 3149.13,2170 D6.2@3154.13,2175
NetD7_2: D7.2 R9.2 | length 176.2
  SIG 1 w10: R9.2 D7.2@3149.13,1870
  SIG 1 w15: D7.2@3149.13,1870 D7.2@3154.13,1875
NetD8_2: D8.2 R10.2 | length 176.2
  SIG 1 w10: R10.2 D8.2@3149.13,1570
  SIG 1 w15: D8.2@3149.13,1570 D8.2@3154.13,1575
NetD9_2: D9.2 R11.2 | length 177.8
  SIG 1 w10: R11.2 D9.2@3149.13,1280
  SIG 1 w15: D9.2@3149.13,1280 D9.2@3154.13,1275
NetR1_1: R1.1 R3.2 U1.1 | length 808
  SIG 1 w10: U1.1 1113.07,1800 1350,1800 ; R3.2 1483.66,1875 1408.66,1800 1350,1800 ; R1.1@1525.62,1624.38 1525.62,1626.74 1507.76,1644.61 1505.39,1644.61 1350,1800
NetR2_2: R2.2 U1.2 | length 404.6
  SIG 1 w10: R2.2 U1.2
PO_PH: J4.2 MD1.19 | length 1238
  SIG 2 w10: MD1.19 3108.02,1209.48 3192.09,1209.48 J4.2
"Pump (Gro)": MD1.7 Q3.1 | length 746.2
  SIG 2 w10: Q3.1 1630,2500 2012.5,2117.5 MD1.7
"Pump (PH+)": MD1.6 Q2.1 | length 1348.2
  SIG 2 w10: Q2.1@1520,3220 1700,3220 1740,3180 1740,2590 2085.96,2244.04 2085.96,2243.9 2100,2229.86 MD1.6
"Pump (PH-)": MD1.5 Q1.1 | length 1991.6
  SIG 2 w10: Q1.1 1740,3940 1940,3740 1940,2477.5 MD1.5
"Pump (Water)": MD1.8 Q4.1 | length 1557.2
  SIG 2 w10: MD1.8 2300,2217.5 2300,2752.76 Q4.1@2822.62,3275.37
Pump(Gro)_LED: MD1.11 R9.1 | length 1034.7
  SIG 1 w10: v2(2825,1870) R9.1
  SIG 2 w10: MD1.11 2100,1729.86 2085.96,1743.9 2085.96,1744.04 2040,1790 2040,1860 2050,1870 v2(2825,1870)
Pump(Gro)_Shunt: MD1.24 Q3.3 R7.1 | length 1508
  SIG 1 w10: R7.1 1821.25,2300 v2(1930,2300)
  SIG 1 w50: Q3.3 R7.1@1781.85,2300
  PWR w10: v2@1928.95,2301.05 1960,2270 2108.08,2270 2408.08,1970 2740,1970 2750,1980 2750,2080 2726.54,2103.46 2726.4,2103.46 2712.36,2117.5 MD1.24
Pump(PH+)_LED: MD1.10 R10.1 | length 905.7
  SIG 1 w10: v2(2825,1575) R10.1@2898.17,1575
  SIG 1 w15: R10.1@2898.17,1575 R10.1
  SIG 2 w10: MD1.10 2247.5,1670 2730,1670 v2(2825,1575)
Pump(PH+)_Shunt: MD1.23 Q2.3 R6.1 | length 1746.9
  SIG 1 w10: R6.1 1831.25,3000 v2(1987,3000)
  SIG 1 w50: Q2.3 1523.75,3001.25 R6.1
  PWR w10: v2(1987,3000) 2520,2467 2520,2197.5 MD1.23
Pump(PH-)_LED: MD1.9 R8.1 | length 905.6
  SIG 1 w10: v2(2825,2170) R8.1
  SIG 2 w10: MD1.9 2497.5,1917.5 2649.43,2069.43 2725.86,2070.86 v2(2825,2170)
Pump(PH-)_Shunt: MD1.22 Q1.3 R4.1 | length 2693.6
  SIG 1 w10: R4.1 1981.21,3725 1986.21,3730 v2(1990,3730)
  SIG 1 w50: Q1.3 1526.18,3740 1541.18,3725 R4.1
  PWR w10: v2(1990,3730) 2780,2940 2780,1925 2772.5,1917.5 MD1.22
Pump(Water)_LED: MD1.12 R11.1 | length 966.2
  SIG 1 w10: v2(2825,1280) R11.1
  SIG 2 w10: MD1.12 2467.5,1250 2792.56,1250 v2@2822.56,1280
  SIG 2 w15: v2@2822.56,1280 v2(2825,1280)
Pump(Water)_Shunt: MD1.25 Q4.3 R5.1 | length 1483.8
  SIG 1 w10: v2(2300,3100) 2300,3225.48 R5.1
  SIG 1 w80: R5.1@2319.52,3225 2572.24,3225 Q4.3
  PWR w10: v2(2300,3100) 2302.68,3097.32 2322.68,3097.32 2600,2820 2600,2317.5 MD1.25
WaterS_1: J6.4 MD1.21 | length 914.8
  SIG 2 w10: MD1.21 3564.35,1817.5 J6.4
pads on no net: J1.3 J2.3 J3.3 J4. J5. J5.2 J6. J6.1 MD1.1 MD1.2 MD1.3 MD1.13 MD1.14 MD1.15 MD1.16 MD1.17 MD1.18 MD1.26 MD1.28

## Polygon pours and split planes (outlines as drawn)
+12 on SIG 1 "+12_L01_P016" (solid, remove dead copper, pour order 16): 3340,3015 3340,2545 3005,2545 3005,3015
GND on SIG 1 "GND_L01_P013" (solid, remove dead copper, pour order 13): 3340,3545 3340,3075 3005,3075 3005,3545
+12 on SIG 1 "+12_L01_P017" (solid, pour order 17): 960,1490 1080,1490 1080,1230 960,1230
+12 on SIG 2 "+12_L03_P015" (solid, remove dead copper, pour order 15): 3340,3015 3340,2545 3005,2545 3005,3015
GND on SIG 2 "GND_L03_P018" (solid, remove dead copper, pour order 18): 3340,3545 3340,3075 3005,3075 3005,3545
+12 on PWR "+12_L04_P019" (solid, remove dead copper, pour order 19): 300,4250 3900,4250 3900,300 3875,325 300,325
GND on PWR "GND_L04_P011" (solid, remove dead copper, pour order 11): 3340,3545 3005,3545 3005,3075 3340,3075
GND on GND (split plane): 3879.9,320.1 320.1,320.1 320.1,4219.9 3879.9,4219.9

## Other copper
SIG 1:
  region net GND: 1970,3295 1970,3160 2145,3160 2145,3295
  rectangle net GND: 1755,1930 1890,2105
  rectangle net GND: 1760,2630 1895,2805
  rectangle net GND: 1755,3350 1890,3525

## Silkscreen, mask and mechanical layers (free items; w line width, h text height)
Top Overlay:
  text "PUMPS" at 760,4070 h60
  text "Water Pump" at 2840,3890 h30
  text "PH-" at 540,3570 h30
  text "+12" at 3655,3485 h30 r270
  text "PH+" at 535,2860 h30
  text "SENSORS" at 3300,2350 h60
  text "!J1!" at 2980,2240 h40
  text "Nutrient" at 530,2140 h30
  text "!J2!" at 2975,1940 h40
  text "Water" at 3725,1925 h30
  text "!J3!" at 3000,1640 h40
  text "!J4!" at 2985,1345 h40
  text "PH" at 3725,1300 h30
  text "EC" at 3725,675 h30
  text "EPICS ASME" at 2675,500 h100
